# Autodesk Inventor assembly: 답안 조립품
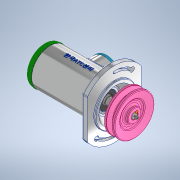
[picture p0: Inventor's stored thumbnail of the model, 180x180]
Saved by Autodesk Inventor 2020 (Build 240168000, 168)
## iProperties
Created: 2022-05
Part Number: 답안 조립품
Document SubType Name: Assembly
Designer: Student
Author: Student
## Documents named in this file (19)
- C:\Users\Student\Desktop\720506V1024\답안 조립품.iam
- C:\Users\Student\Desktop\720506V1024\본체.ipt
- C:\Users\Student\Desktop\720506V1024\사이드 커버.ipt
- 사이드 커버.ipt
- C:\Users\Student\Desktop\720506V1024\베어링 6202.ipt
- C:\Users\Student\Desktop\720506V1024\축.ipt
- C:\Users\Student\Desktop\720506V1024\멈춤링 35 x 1.6.ipt
- C:\Users\Student\Desktop\720506V1024\멈춤링 15 x 1.ipt
- C:\Users\Student\Desktop\720506V1024\개스킷.ipt
- C:\Users\Student\Desktop\720506V1024\탑 커버.ipt
- C:\Users\Student\Desktop\720506V1024\키 4 x 4.ipt
- C:\Users\Student\Desktop\720506V1024\오일 실 15 x 30 x 7.ipt
- C:\Users\Student\Desktop\720506V1024\부시2.ipt
- C:\Users\Student\Desktop\720506V1024\와셔 10 x 21.ipt
- C:\Users\Student\Desktop\720506V1024\너트 M10.ipt
- C:\Users\Student\Desktop\720506V1024\V-벨트풀리.ipt
- C:\Users\Student\Desktop\720506V1024\와셔 4 x 16.ipt
- C:\Users\Student\Desktop\720506V1024\십자볼트 M3 x 10.ipt
- C:\Users\Student\Desktop\720506V1024\부시1.ipt
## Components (2 placed, 2 different names)
1. 개스킷:1
2. V-벨트풀리:1
